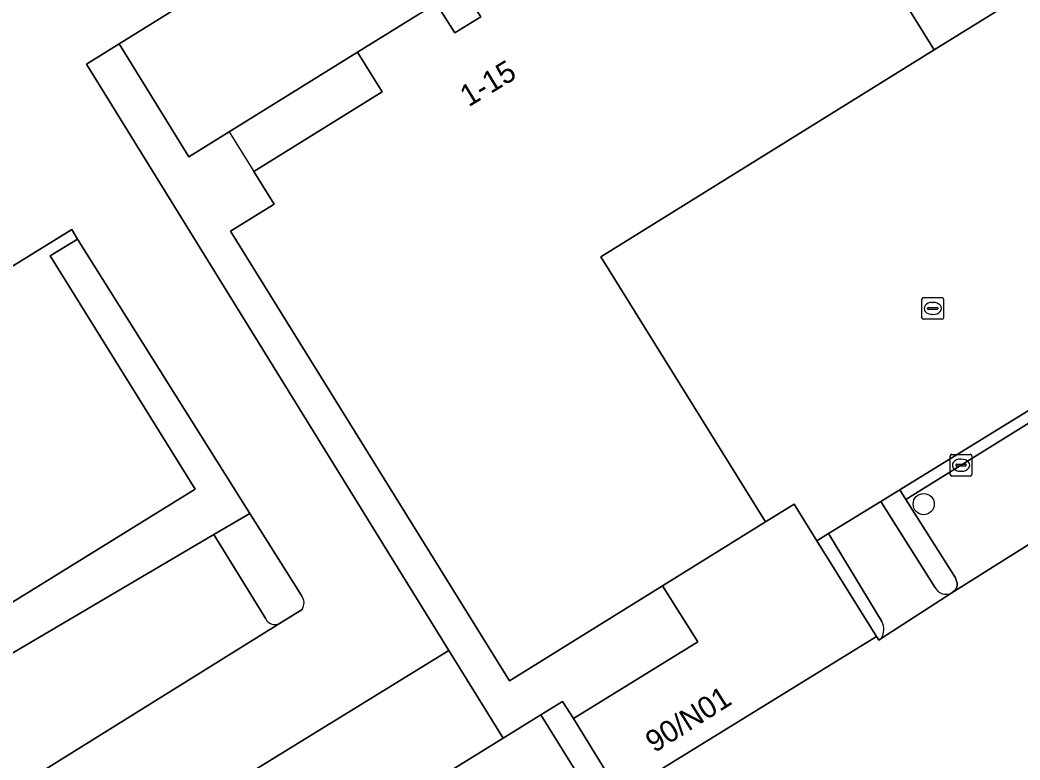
# Model space of a CAD drawing. Extents: x 160304 to 160955, y 383684 to 384161.
# Drawn here: x 160703.42 to 160749.55, y 384039.97 to 384074.11 of the extents above; entities that cross this region are included whole.
import ezdxf

# ---------------------------------------------------------------- set-up
doc = ezdxf.new("R2010")
doc.units = 0
for name, color, linetype in [('IMGEO_Boom', 7, 'Continuous'), ('IMGEO_Erf', 7, 'Continuous'), ('IMGEO_Hek', 7, 'Continuous'), ('IMGEO_Kolk', 7, 'Continuous'), ('IMGEO_Pand', 7, 'Continuous'), ('IMGEO_Pand_nummerreeks', 7, 'Continuous'), ('IMGEO_Pand_overbouw', 7, 'Continuous'), ('IMGEO_Parkeervlak_open', 7, 'Continuous'), ('IMGEO_Rijbaan_lokaal_open', 7, 'Continuous'), ('IMGEO_Rioolput', 7, 'Continuous'), ('IMGEO_Verkeerseiland_open', 7, 'Continuous'), ('IMGEO_Voetpad_open', 7, 'Continuous')]:
    doc.layers.add(name, color=color, linetype=linetype)

msp = doc.modelspace()

# ---------------------------------------------------------------- linework, layer by layer
at = {"layer": 'IMGEO_Boom'}
msp.add_circle((160745.113, 384051.777), 0.489, dxfattribs=at)
at = {"layer": 'IMGEO_Erf'}
msp.add_lwpolyline([(160753.846, 384077.856), (160745.599, 384072.736), (160730.219, 384063.187), (160737.814, 384050.953), (160739.131, 384051.771), (160740.182, 384050.089), (160740.719, 384050.419), (160743.128, 384051.901), (160744.005, 384052.44), (160744.052, 384052.469), (160762.47, 384063.798)], dxfattribs=at)
msp.add_lwpolyline([(160731.111, 384038.375), (160728.947, 384041.881), (160728.446, 384042.674), (160727.453, 384042.058), (160730.119, 384037.755)], close=True, dxfattribs=at)
at = {"layer": 'IMGEO_Hek'}
for points in [[(160762.47, 384063.798), (160744.052, 384052.469)], [(160744.052, 384052.469), (160743.128, 384051.901)], [(160743.128, 384051.901), (160740.719, 384050.419)], [(160740.719, 384050.419), (160740.182, 384050.089)]]:
    msp.add_lwpolyline(points, dxfattribs=at)
at = {"layer": 'IMGEO_Kolk'}
for p, q in [((160746.335, 384053.147), (160746.335, 384053.999)), ((160746.41, 384054.073), (160747.262, 384054.073)), ((160746.823, 384053.853), (160746.848, 384053.853)), ((160747.336, 384053.999), (160747.336, 384053.147)), ((160746.594, 384053.567), (160746.594, 384053.579)), ((160747.032, 384053.53), (160746.634, 384053.53)), ((160746.637, 384053.616), (160747.035, 384053.616)), ((160746.846, 384053.293), (160746.821, 384053.293)), ((160747.078, 384053.579), (160747.078, 384053.567)), ((160747.262, 384053.073), (160746.41, 384053.073))]:
    msp.add_line(p, q, dxfattribs=at)
for points in [[(160746.335, 384053.147), (160746.335, 384053.999)], [(160746.41, 384054.073), (160747.262, 384054.073)], [(160747.336, 384053.999), (160747.336, 384053.147)], [(160747.262, 384053.073), (160746.41, 384053.073)]]:
    msp.add_lwpolyline(points, dxfattribs=at)
for centre, radius, start, end in [((160746.412, 384053.997), 0.0765, 91.552, 178.448), ((160746.412, 384053.997), 0.0765, 91.552, 178.448), ((160747.26, 384053.997), 0.0765, 1.552, 88.448), ((160747.26, 384053.997), 0.0765, 1.552, 88.448), ((160746.634, 384053.576), 0.0403, 85.8775, 175.7526), ((160746.631, 384053.566), 0.0366, 178.938, 274.7102), ((160747.035, 384053.573), 0.043, 264.8664, 352.4533), ((160747.039, 384053.578), 0.0386, 1.7309, 96.639), ((160746.412, 384053.149), 0.0765, 181.552, 268.448), ((160746.412, 384053.149), 0.0765, 181.552, 268.448), ((160747.26, 384053.149), 0.0765, 271.552, 358.448), ((160747.26, 384053.149), 0.0765, 271.552, 358.448)]:
    msp.add_arc(centre, radius, start, end, dxfattribs=at)
for centre, major_axis, ratio, start_param, end_param in [((160746.822, 384053.573), (-0.387, 0.002), 0.722429, 4.712389, 7.853982), ((160746.847, 384053.573), (-0.39, 0.002), 0.717154, 1.570796, 4.712389)]:
    msp.add_ellipse(centre, major_axis=major_axis, ratio=ratio, start_param=start_param, end_param=end_param, dxfattribs=at)
at = {"layer": 'IMGEO_Pand'}
for points in [[(160745.599, 384072.736), (160738.24, 384084.566), (160723.825, 384075.6), (160724.675, 384074.255), (160723.472, 384073.526), (160722.622, 384074.871), (160718.989, 384072.622), (160720.124, 384070.796), (160714.211, 384067.125), (160715.145, 384065.622), (160713.123, 384064.367), (160726.004, 384043.621), (160733.056, 384047.999), (160737.814, 384050.953), (160730.219, 384063.187)], [(160737.814, 384050.953), (160733.056, 384047.999), (160734.692, 384045.426), (160728.947, 384041.881), (160731.111, 384038.375), (160742.941, 384045.675), (160740.182, 384050.089), (160739.131, 384051.771)]]:
    msp.add_lwpolyline(points, close=True, dxfattribs=at)
for points in [[(160738.24, 384084.566), (160745.599, 384072.736), (160753.846, 384077.856), (160762.238, 384064.34), (160763.615, 384065.195), (160763.926, 384064.694), (160764.48, 384063.803), (160773.141, 384069.188), (160772.246, 384070.611), (160763.696, 384084.339)], [(160694.629, 384042.042), (160711.18, 384052.269), (160711.492, 384052.462), (160704.809, 384063.238), (160706.073, 384064.001), (160705.803, 384064.45), (160692.014, 384055.93)]]:
    msp.add_lwpolyline(points, dxfattribs=at)
at = {"layer": 'IMGEO_Pand_overbouw'}
msp.add_lwpolyline([(160720.124, 384070.796), (160718.989, 384072.622), (160713.071, 384068.959), (160714.211, 384067.125)], close=True, dxfattribs=at)
at = {"layer": 'IMGEO_Parkeervlak_open'}
for points in [[(160761.845, 384089.993), (160762.626, 384088.748), (160763.201, 384089.104), (160755.07, 384102.215), (160707.989, 384073.011), (160711.21, 384067.807), (160718.989, 384072.622), (160722.622, 384074.871), (160723.472, 384073.526), (160724.675, 384074.255), (160723.825, 384075.6), (160738.24, 384084.566)], [(160714.759, 384046.478), (160712.354, 384050.369), (160695.582, 384040.495), (160690.89, 384037.575), (160691.762, 384036.175), (160693.825, 384032.859), (160701.722, 384037.769), (160715.395, 384046.269)]]:
    msp.add_lwpolyline(points, dxfattribs=at)
for points in [[(160746.411, 384047.687), (160760.813, 384056.736), (160758.349, 384060.731), (160744.284, 384051.986), (160746.574, 384048.369), (160746.616, 384048.274), (160746.65, 384048.147), (160746.657, 384048.014), (160746.631, 384047.898), (160746.576, 384047.814)], [(160715.343, 384034.554), (160720.51, 384037.766), (160725.711, 384040.981), (160723.208, 384045.029), (160701.692, 384031.792), (160696.482, 384028.586), (160699.065, 384024.433), (160701.775, 384026.118), (160706.863, 384029.281)]]:
    msp.add_lwpolyline(points, close=True, dxfattribs=at)
msp.add_arc((160715.179, 384046.683), 0.467, 206.0005, 297.6168, dxfattribs=at)
at = {"layer": 'IMGEO_Rijbaan_lokaal_open'}
for points in [[(160706.486, 384072.081), (160707.989, 384073.011), (160755.07, 384102.215), (160751.853, 384107.403), (160740.525, 384100.316), (160706.032, 384078.853), (160703.145, 384077.057), (160703.048, 384077.225)], [(160716.431, 384046.914), (160715.395, 384046.269), (160701.722, 384037.769), (160693.825, 384032.859), (160695.799, 384029.684), (160696.482, 384028.586), (160701.692, 384031.792), (160723.208, 384045.029), (160706.486, 384072.081)], [(160692.014, 384055.93), (160705.803, 384064.45), (160706.073, 384064.001), (160714.021, 384051.35), (160716.402, 384047.56)], [(160760.813, 384056.736), (160746.411, 384047.687), (160743.153, 384045.579), (160743.045, 384045.504), (160742.941, 384045.675), (160731.111, 384038.375)]]:
    msp.add_lwpolyline(points, dxfattribs=at)
msp.add_arc((160715.974, 384047.217), 0.548, 326.4399, 38.7009, dxfattribs=at)
at = {"layer": 'IMGEO_Rioolput'}
for p, q in [((160745.029, 384060.379), (160745.029, 384061.231)), ((160745.104, 384061.305), (160745.956, 384061.305)), ((160745.517, 384061.085), (160745.542, 384061.085)), ((160746.03, 384061.231), (160746.03, 384060.379)), ((160745.288, 384060.799), (160745.288, 384060.811)), ((160745.726, 384060.762), (160745.328, 384060.762)), ((160745.331, 384060.848), (160745.729, 384060.848)), ((160745.772, 384060.811), (160745.772, 384060.799)), ((160745.956, 384060.305), (160745.104, 384060.305)), ((160745.54, 384060.525), (160745.515, 384060.525))]:
    msp.add_line(p, q, dxfattribs=at)
for points in [[(160745.029, 384060.379), (160745.029, 384061.231)], [(160745.104, 384061.305), (160745.956, 384061.305)], [(160746.03, 384061.231), (160746.03, 384060.379)], [(160745.956, 384060.305), (160745.104, 384060.305)]]:
    msp.add_lwpolyline(points, dxfattribs=at)
for centre, radius, start, end in [((160745.106, 384061.229), 0.0765, 91.552, 178.448), ((160745.106, 384061.229), 0.0765, 91.552, 178.448), ((160745.954, 384061.229), 0.0765, 1.552, 88.448), ((160745.954, 384061.229), 0.0765, 1.552, 88.448), ((160745.328, 384060.808), 0.0403, 85.8775, 175.7526), ((160745.325, 384060.798), 0.0366, 178.938, 274.7102), ((160745.729, 384060.805), 0.043, 264.8664, 352.4533), ((160745.733, 384060.81), 0.0386, 1.7309, 96.639), ((160745.106, 384060.381), 0.0765, 181.552, 268.448), ((160745.106, 384060.381), 0.0765, 181.552, 268.448), ((160745.954, 384060.381), 0.0765, 271.552, 358.448), ((160745.954, 384060.381), 0.0765, 271.552, 358.448)]:
    msp.add_arc(centre, radius, start, end, dxfattribs=at)
for centre, major_axis, ratio, start_param, end_param in [((160745.516, 384060.805), (-0.387, 0.002), 0.722429, 4.712389, 7.853982), ((160745.541, 384060.805), (-0.39, 0.002), 0.717154, 1.570796, 4.712389)]:
    msp.add_ellipse(centre, major_axis=major_axis, ratio=ratio, start_param=start_param, end_param=end_param, dxfattribs=at)
at = {"layer": 'IMGEO_Verkeerseiland_open'}
msp.add_lwpolyline([(160743.18, 384046.354), (160740.719, 384050.419), (160740.182, 384050.089), (160742.941, 384045.675), (160743.045, 384045.504), (160743.153, 384045.579)], dxfattribs=at)
msp.add_arc((160742.508, 384045.989), 0.765, 327.5462, 28.4632, dxfattribs=at)
at = {"layer": 'IMGEO_Voetpad_open'}
for points in [[(160714.211, 384067.125), (160720.124, 384070.796), (160718.989, 384072.622), (160711.21, 384067.807), (160707.989, 384073.011), (160706.486, 384072.081), (160723.208, 384045.029), (160725.711, 384040.981), (160727.453, 384042.058), (160728.446, 384042.674), (160728.947, 384041.881), (160734.692, 384045.426), (160733.056, 384047.999), (160726.004, 384043.621), (160713.123, 384064.367), (160715.145, 384065.622)], [(160714.021, 384051.35), (160706.073, 384064.001), (160704.809, 384063.238), (160711.492, 384052.462), (160711.18, 384052.269), (160694.629, 384042.042), (160695.582, 384040.495), (160712.354, 384050.369)], [(160762.47, 384063.798), (160744.052, 384052.469), (160744.005, 384052.44), (160744.284, 384051.986), (160758.349, 384060.731), (160760.813, 384056.736), (160765.15, 384059.428)]]:
    msp.add_lwpolyline(points, close=True, dxfattribs=at)
for points in [[(160744.284, 384051.986), (160744.005, 384052.44), (160743.128, 384051.901), (160745.632, 384047.952)], [(160745.632, 384047.952), (160743.128, 384051.901), (160740.719, 384050.419), (160743.18, 384046.354)], [(160746.411, 384047.687), (160746.576, 384047.814), (160746.631, 384047.898), (160746.657, 384048.014), (160746.65, 384048.147), (160746.616, 384048.274), (160746.574, 384048.369), (160744.284, 384051.986)], [(160714.021, 384051.35), (160712.354, 384050.369), (160714.759, 384046.478)], [(160716.402, 384047.56), (160714.021, 384051.35)], [(160743.153, 384045.579), (160746.411, 384047.687)], [(160715.395, 384046.269), (160716.431, 384046.914)], [(160730.119, 384037.755), (160727.453, 384042.058), (160725.711, 384040.981), (160720.51, 384037.766)]]:
    msp.add_lwpolyline(points, dxfattribs=at)
for centre, radius, start, end in [((160746.138, 384048.163), 0.549, 202.6426, 299.7829), ((160746.138, 384048.163), 0.549, 202.6426, 299.7829), ((160715.974, 384047.217), 0.548, 326.4399, 38.7009), ((160715.179, 384046.683), 0.467, 206.0005, 297.6168), ((160742.508, 384045.989), 0.765, 327.5462, 28.4632)]:
    msp.add_arc(centre, radius, start, end, dxfattribs=at)

# ---------------------------------------------------------------- texts
at = {"layer": 'IMGEO_Pand_nummerreeks'}
for s, rotation, p in [('1-15', 31.2152, (160724.113, 384070.079)), ('90/N01', 32.3302, (160732.687, 384040.279))]:
    msp.add_text(s, height=1, rotation=rotation, dxfattribs=at).set_placement(p)

doc.saveas('drawing.dxf')
